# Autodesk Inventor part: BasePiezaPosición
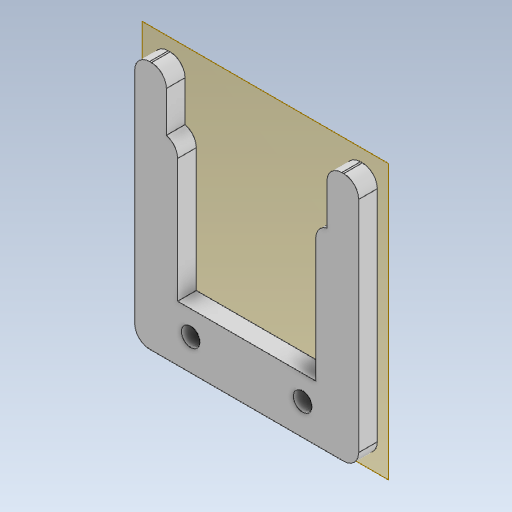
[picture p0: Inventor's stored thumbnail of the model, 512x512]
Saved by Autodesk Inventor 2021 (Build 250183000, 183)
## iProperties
Created: 2021-02
Part Number: BasePiezaPosición
Material: Genérico
Document SubType Name: Modeling
Designer: ATOUZA
Density: 1 g/cm^3
Appearance: Valor por defecto
Author: ATOUZA
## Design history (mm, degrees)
node "Plano de trabajo1"
node "Plano de trabajo2"
sketch "Boceto1"
  geometry: L1 (-26, -33.365)-(26, -33.365) reference; L2 (30, -29.365)-(30, 29.365) reference; L3 (-30, 29.365)-(-30, -29.365) reference; L4 (18.5, -18.5)-(-18.5, -18.5); L5 (-18.5, -18.5)-(-18.5, 18.5); L6 (18.5, 18.5)-(18.5, -18.5); L7 (18.5, -18.5)-(-18.5, 18.5); L8 (-18.5, -18.5)-(18.5, 18.5); L9 (-18.5, 18.5)-(-21.5, 18.5); L10 (-21.5, 18.5)-(-21.5, 33.365); L11 (18.5, 18.5)-(21.5, 18.5); L12 (21.5, 18.5)-(21.5, 33.365); L13 (26, 33.365)-(21.5, 33.365); L14 (-21.5, 33.365)-(-26, 33.365); C1 r 2.5 at (-15, -25) reference; C2 r 2.5 at (15, -25) reference; A1 r 4 centre (-26, -29.365) between (-30, -29.365) and (-26, -33.365) reference; A2 r 4 centre (26, -29.365) between (26, -33.365) and (30, -29.365) reference; A3 r 4 centre (26, 29.365) between (30, 29.365) and (26, 33.365) reference; A4 r 4 centre (-26, 29.365) between (-26, 33.365) and (-30, 29.365) reference; 1 further point
  constraints: 22 end point, 2 midpoint, 1 horizontal, 1 parallel, 1 perpendicular, 1 point on line
  dimensions: "d4" = 37 distance of L4.end L5.end; "d5" = 37 distance of L4.start L4.end; "d6" = 3 distance between parallel lines of L10 L5; "d7" = 3 distance between parallel lines of L12 L6
extrude "Extrusión1" new body sketch "Boceto1" distance "d8" = 5; taper "d9" = 0 deg
fillet "Empalme1" dims "d10" = 4
node "Sólido1"
